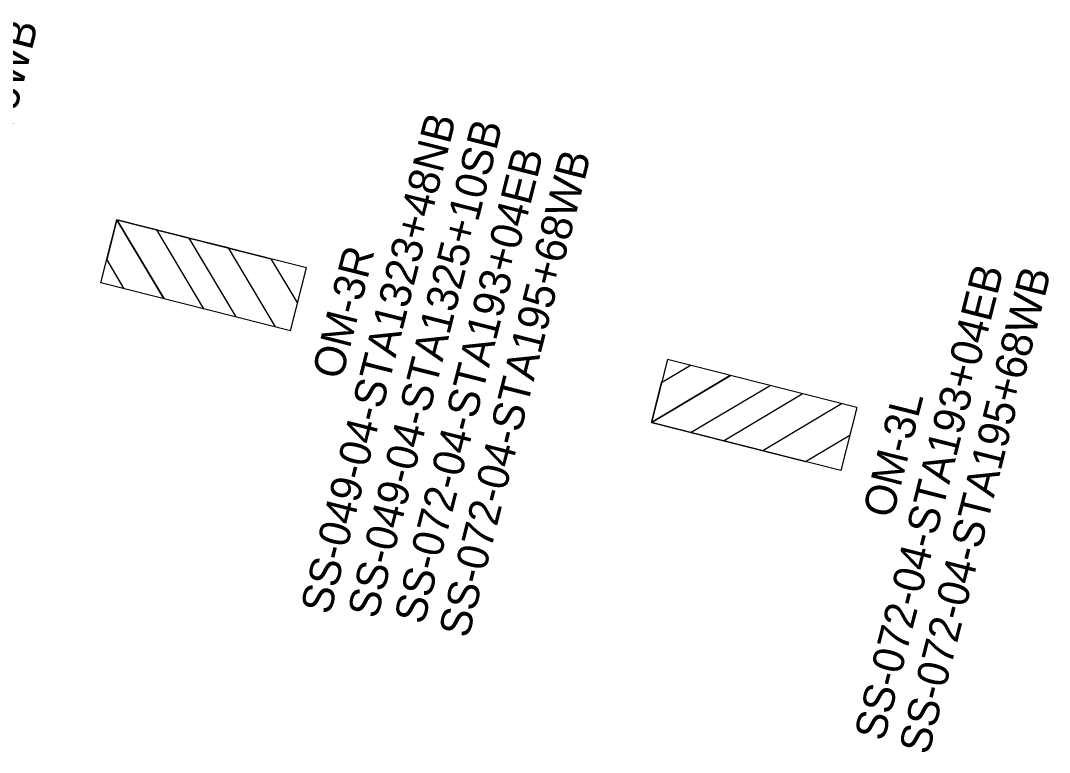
# Model space of a CAD drawing. Extents: x 670257 to 671518, y 737783 to 738188.
# Drawn here: x 670284.54 to 670292.82, y 738140.39 to 738146.29 of the extents above; entities that cross this region are included whole.
import ezdxf

# ---------------------------------------------------------------- set-up
doc = ezdxf.new("R2010")
doc.units = 0
for name, color, linetype in [('Default', 7, 'Continuous'), ('R_SIGN_ANNOT_HWY72', 7, 'Continuous'), ('R_SIGN_HWY72', 7, 'Continuous')]:
    doc.layers.add(name, color=color, linetype=linetype)

msp = doc.modelspace()

# ---------------------------------------------------------------- linework, layer by layer
at = {"layer": 'R_SIGN_HWY72'}
for p, q in [((670285.1826, 738144.1733), (670285.3116, 738144.682)), ((670285.1826, 738144.1733), (670285.3116, 738144.682)), ((670285.3116, 738144.682), (670285.2298, 738144.3595)), ((670286.8377, 738144.295), (670285.3116, 738144.682)), ((670285.3116, 738144.682), (670286.5526, 738144.3673)), ((670286.8377, 738144.295), (670285.3116, 738144.682)), ((670285.3116, 738144.682), (670285.6913, 738144.0443)), ((670285.3116, 738144.682), (670285.6896, 738144.0471)), ((670285.6896, 738144.0471), (670285.3116, 738144.682)), ((670286.011, 738143.9657), (670285.633, 738144.6007)), ((670285.8916, 738144.5349), (670286.2696, 738143.9)), ((670286.2097, 738144.4554), (670285.8916, 738144.5349)), ((670286.5877, 738143.8205), (670286.2097, 738144.4554)), ((670285.2298, 738144.3595), (670285.3682, 738144.127)), ((670286.5526, 738144.3673), (670286.7654, 738144.0099)), ((670286.7087, 738143.7863), (670286.8377, 738144.295)), ((670286.7087, 738143.7863), (670286.8377, 738144.295)), ((670286.7087, 738143.7863), (670285.1826, 738144.1733)), ((670289.7457, 738143.5575), (670289.6166, 738143.0488)), ((670289.7457, 738143.5575), (670289.6166, 738143.0488)), ((670289.6984, 738143.3713), (670289.9309, 738143.5097)), ((670291.2718, 738143.1704), (670289.7457, 738143.5575)), ((670289.6166, 738143.0488), (670290.2543, 738143.4285)), ((670289.6166, 738143.0488), (670290.2516, 738143.4268)), ((670290.2516, 738143.4268), (670289.6166, 738143.0488)), ((670289.6166, 738143.0488), (670289.6984, 738143.3713)), ((670290.5729, 738143.3452), (670289.938, 738142.9671)), ((670290.1966, 738142.9017), (670290.8316, 738143.2797)), ((670291.1491, 738143.198), (670290.5141, 738142.82)), ((670291.2718, 738143.1704), (670291.1428, 738142.6617)), ((670291.2718, 738143.1704), (670291.1428, 738142.6617)), ((670291.1428, 738142.6617), (670289.6166, 738143.0488)), ((670289.6166, 738143.0488), (670290.8576, 738142.734)), ((670291.1428, 738142.6617), (670289.6166, 738143.0488)), ((670290.5141, 738142.82), (670290.1966, 738142.9017)), ((670290.8576, 738142.734), (670291.2151, 738142.9468))]:
    msp.add_line(p, q, dxfattribs=at)

# ---------------------------------------------------------------- texts
at = {"layer": 'Default'}
msp.add_text('SS-072-04-STA202+75WB', height=0.25, rotation=75.76854, dxfattribs=at).set_placement((670283.69, 738142.3562))
at = {"layer": 'R_SIGN_ANNOT_HWY72'}
for s, p in [('SS-049-04-STA1323+48NB', (670287.0297, 738141.4929)), ('SS-049-04-STA1325+10SB', (670287.4082, 738141.4598)), ('SS-072-04-STA193+04EB', (670287.7833, 738141.4134)), ('SS-072-04-STA195+68WB', (670288.1425, 738141.3041)), ('OM-3R', (670287.1231, 738143.3863)), ('SS-072-04-STA193+04EB', (670291.4904, 738140.4733)), ('SS-072-04-STA195+68WB', (670291.8495, 738140.3639)), ('OM-3L', (670291.5588, 738142.2684))]:
    msp.add_text(s, height=0.25, rotation=75.76855, dxfattribs=at).set_placement(p)

doc.saveas('drawing.dxf')
